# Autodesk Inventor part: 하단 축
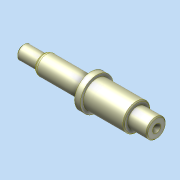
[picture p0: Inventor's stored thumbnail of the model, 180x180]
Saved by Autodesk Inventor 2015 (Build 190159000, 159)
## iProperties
Created: 2024-05
Part Number: 하단 축
Material: 일반
Document SubType Name: Modeling
Designer: Administrator
Density: 1 g/cm^3
Appearance: 기본값
Author: Administrator
Author: jhkim
Creation Date: 2024-05-07
Sending System: Autodesk Inventor 2025
Preprocessor: ST-DEVELOPER v20
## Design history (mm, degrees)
node "하단 축1"
node "솔리드1"
node "기준1"
